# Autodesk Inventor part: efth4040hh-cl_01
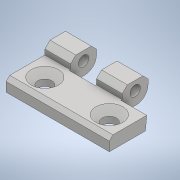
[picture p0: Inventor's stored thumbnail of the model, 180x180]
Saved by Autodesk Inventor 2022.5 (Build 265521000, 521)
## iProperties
Part Number: efth4040hh-cl_01
Material: 一般
Document SubType Name: Modeling
Designer: ImaoCorp
Density: 1 g/cm^3
Appearance: 既定
Author: ImaoCorp
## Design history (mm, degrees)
feature "efth4040hh-cl_01"
node "ソリッド1"
